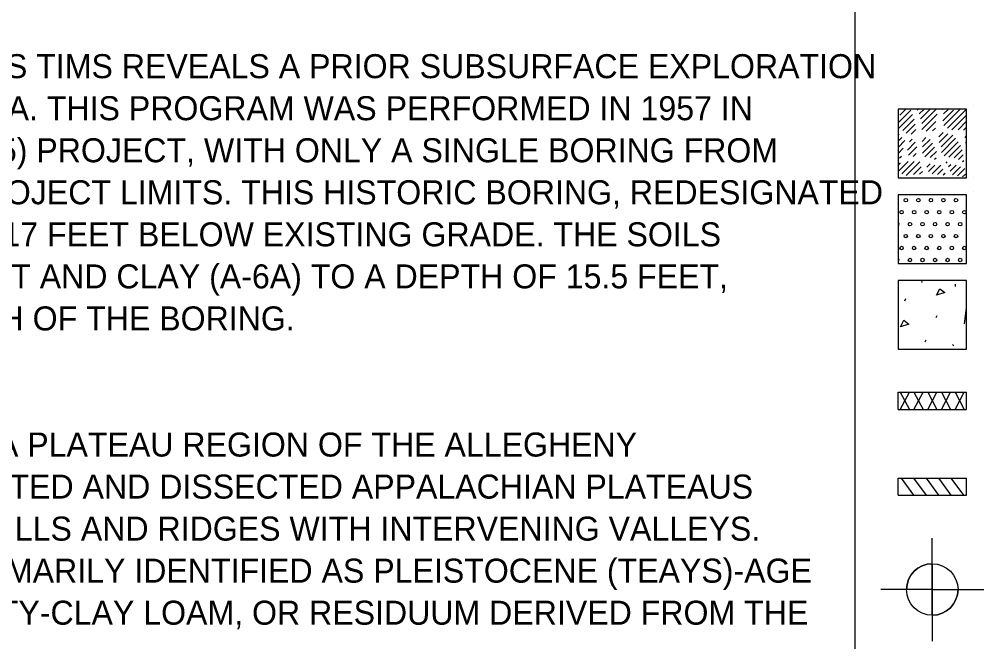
# Model space of a CAD drawing. Extents: x 0 to 34, y -8.9 to 22.
# Drawn here: x 6.83 to 12.45, y 14.31 to 17.94 of the extents above; entities that cross this region are included whole.
import ezdxf

# ---------------------------------------------------------------- set-up
doc = ezdxf.new("R2010")
doc.units = 0
for name, color, linetype in [('Default', 7, 'Continuous'), ('GT_Project_Soil_Boring', 7, 'Continuous'), ('GT_Project_Soil_Layers', 7, 'Continuous'), ('SH_Data', 7, 'Continuous'), ('SH_Text', 7, 'Continuous')]:
    doc.layers.add(name, color=color, linetype=linetype)

msp = doc.modelspace()

# ---------------------------------------------------------------- linework, layer by layer
at = {"layer": 'Default'}
for p, q in [((11.9545, 17.4334), (11.9545, 17.4334)), ((11.9597, 17.3384), (12.0303, 17.4089)), ((11.9652, 17.3792), (12.001, 17.415)), ((12.0664, 17.4097), (12.0717, 17.415)), ((12.0788, 17.3868), (12.107, 17.415)), ((12.0863, 17.3589), (12.1416, 17.4142)), ((12.0927, 17.33), (12.1767, 17.4139)), ((12.2121, 17.414), (12.2131, 17.415)), ((12.2158, 17.347), (12.2777, 17.4089)), ((12.2204, 17.3869), (12.2465, 17.413)), ((12.2228, 17.3187), (12.3178, 17.4136)), ((12.2437, 17.3041), (12.3493, 17.4098)), ((12.394, 17.4334), (12.394, 17.4334)), ((11.9602, 17.3035), (12.0398, 17.3832)), ((11.9827, 17.2907), (12.048, 17.356)), ((12.0939, 17.2958), (12.1827, 17.3846)), ((12.1187, 17.2853), (12.1752, 17.3418)), ((12.2694, 17.2945), (12.3545, 17.3797)), ((12.3048, 17.2945), (12.3545, 17.3443)), ((12.0029, 17.2755), (12.055, 17.3276)), ((12.0307, 17.2679), (12.058, 17.2953)), ((12.1563, 17.2875), (12.173, 17.3042)), ((12.1928, 17.2532), (12.2171, 17.2776)), ((12.3369, 17.2913), (12.3545, 17.3089)), ((11.9545, 17.2625), (11.9604, 17.2683)), ((11.9545, 17.2271), (11.9774, 17.25)), ((11.9545, 17.1918), (11.9944, 17.2316)), ((12.0099, 17.1764), (12.0548, 17.2214)), ((12.0219, 17.2237), (12.0372, 17.2391)), ((12.0953, 17.2265), (12.1175, 17.2486)), ((12.0971, 17.1575), (12.1561, 17.2166)), ((12.0983, 17.1941), (12.1418, 17.2376)), ((12.1945, 17.2196), (12.2454, 17.2705)), ((12.2055, 17.1953), (12.2739, 17.2637)), ((12.2074, 17.1618), (12.2906, 17.245)), ((12.2233, 17.1424), (12.3055, 17.2245)), ((12.3446, 17.2484), (12.3545, 17.2584)), ((12.3491, 17.2176), (12.3545, 17.223)), ((11.9545, 17.1564), (11.9846, 17.1865)), ((12.0162, 17.1473), (12.0639, 17.1951)), ((12.1119, 17.137), (12.1676, 17.1927)), ((12.142, 17.1318), (12.1783, 17.1681)), ((12.251, 17.1347), (12.3185, 17.2022)), ((12.2818, 17.1302), (12.3283, 17.1767)), ((11.9545, 17.0504), (12.013, 17.1088)), ((11.9637, 17.1302), (11.9747, 17.1412)), ((11.9771, 17.0376), (12.049, 17.1094)), ((12.0023, 17.0275), (12.0822, 17.1073)), ((12.0423, 17.1381), (12.061, 17.1569)), ((12.1682, 17.1226), (12.1763, 17.1307)), ((12.2346, 17.1001), (12.2415, 17.107)), ((12.3075, 17.1204), (12.3356, 17.1486)), ((12.3313, 17.1089), (12.3382, 17.1158)), ((11.9545, 17.0857), (11.9699, 17.1011)), ((12.0447, 17.0345), (12.0889, 17.0787)), ((12.0805, 17.0349), (12.0966, 17.0511)), ((12.123, 17.0774), (12.1421, 17.0965)), ((12.1331, 17.0521), (12.1691, 17.0882)), ((12.1536, 17.0373), (12.2038, 17.0875)), ((12.1845, 17.0329), (12.2156, 17.064)), ((12.2494, 17.0795), (12.2627, 17.0929)), ((12.2593, 17.054), (12.2936, 17.0884)), ((12.272, 17.0315), (12.3187, 17.0781)), ((12.3013, 17.0254), (12.3438, 17.0679)), ((11.9545, 17.015), (11.9545, 17.015)), ((12.2187, 17.0317), (12.2289, 17.0419)), ((12.3312, 17.0199), (12.3477, 17.0364)), ((12.394, 17.015), (12.394, 17.015)), ((11.9545, 16.9334), (11.9545, 16.9334)), ((12.394, 16.9334), (12.394, 16.9334)), ((11.9545, 16.7538), (11.9545, 16.7351)), ((11.9545, 16.5447), (11.9545, 16.526)), ((11.9545, 16.515), (11.9545, 16.515)), ((12.0918, 16.415), (12.0929, 16.4049)), ((12.2874, 16.3947), (12.2889, 16.3814)), ((11.9944, 16.2975), (12.0003, 16.3108)), ((12.1774, 16.1995), (12.1833, 16.2128)), ((12.3417, 16.1635), (12.3545, 16.256)), ((12.1125, 16.0578), (12.1185, 16.0711)), ((12.2733, 16.0439), (12.2793, 16.035)), ((11.9545, 16.015), (11.9545, 16.015))]:
    msp.add_line(p, q, dxfattribs=at)
for points in [[(12.1799, 16.3312), (12.1976, 16.3682), (12.2272, 16.346), (12.1799, 16.3312)], [(11.9698, 16.1469), (11.9876, 16.1839), (12.0172, 16.1617), (11.9698, 16.1469)]]:
    msp.add_lwpolyline(points, dxfattribs=at)
for centre in [(11.9999, 16.8839), (12.0731, 16.8839), (12.1463, 16.8839), (12.2196, 16.8839), (12.2928, 16.8839), (11.9754, 16.8142), (12.0486, 16.8142), (12.1219, 16.8142), (12.1951, 16.8142), (12.2684, 16.8142), (12.3415, 16.8142), (12.0242, 16.7445), (12.0974, 16.7445), (12.1707, 16.7445), (12.2439, 16.7445), (12.317, 16.7445), (11.9998, 16.6748), (12.073, 16.6748), (12.1462, 16.6748), (12.2195, 16.6748), (12.2926, 16.6748), (11.9753, 16.6051), (12.0485, 16.6051), (12.1218, 16.6051), (12.195, 16.6051), (12.2683, 16.6051), (12.3414, 16.6051), (12.0241, 16.5354), (12.0973, 16.5354), (12.1706, 16.5354), (12.2438, 16.5354), (12.3169, 16.5354)]:
    msp.add_circle(centre, 0.01, dxfattribs=at)
for centre, start, end in [((11.951, 16.7445), 290.8521, 69.1479), ((11.9509, 16.5354), 291.3407, 68.6593)]:
    msp.add_arc(centre, 0.01, start, end, dxfattribs=at)
at = {"layer": 'GT_Project_Soil_Boring'}
for p, q in [((12.1545, 14.615), (12.1545, 14.915)), ((12.1545, 14.765), (12.1545, 14.615)), ((12.1545, 14.615), (11.8545, 14.615)), ((12.1545, 14.615), (12.0045, 14.615)), ((12.1545, 14.615), (12.1545, 14.3149)), ((12.1545, 14.615), (12.4545, 14.615)), ((12.1545, 14.465), (12.1545, 14.615)), ((12.1545, 14.615), (12.3045, 14.615))]:
    msp.add_line(p, q, dxfattribs=at)
msp.add_circle((12.1545, 14.615), 0.15, dxfattribs=at)
for start, end in [(90, 180), (270, 360)]:
    msp.add_arc((12.1545, 14.615), 0.15, start, end, dxfattribs=at)
at = {"layer": 'GT_Project_Soil_Layers'}
for p, q in [((11.9678, 15.7649), (12.0212, 15.665)), ((11.9678, 15.665), (12.0212, 15.7649)), ((12.0478, 15.665), (12.1012, 15.7649)), ((12.0478, 15.7649), (12.1012, 15.665)), ((12.1278, 15.7649), (12.1812, 15.665)), ((12.1278, 15.665), (12.1812, 15.7649)), ((12.2078, 15.7649), (12.2612, 15.665)), ((12.2078, 15.665), (12.2612, 15.7649)), ((12.2878, 15.7649), (12.3412, 15.665)), ((12.2878, 15.665), (12.3412, 15.7649)), ((11.9727, 15.2649), (12.0454, 15.165)), ((12.0454, 15.2649), (12.1181, 15.165)), ((12.1181, 15.2649), (12.1909, 15.165)), ((12.1909, 15.2649), (12.2636, 15.165)), ((12.2636, 15.2649), (12.3363, 15.165))]:
    msp.add_line(p, q, dxfattribs=at)
at = {"layer": 'SH_Data'}
for p, q in [((11.7045, 1.1573), (11.7045, 21.5)), ((11.9545, 15.665), (11.9545, 15.7649)), ((11.9545, 15.7649), (12.3545, 15.7649)), ((12.3545, 15.665), (12.3545, 15.7649)), ((11.9545, 15.665), (12.3545, 15.665)), ((11.9545, 15.165), (11.9545, 15.2649)), ((11.9545, 15.2649), (12.3545, 15.2649)), ((12.3545, 15.165), (12.3545, 15.2649)), ((11.9545, 15.165), (12.3545, 15.165))]:
    msp.add_line(p, q, dxfattribs=at)
for points in [[(11.9545, 17.015), (12.3545, 17.015), (12.3545, 17.415), (11.9545, 17.415)], [(11.9545, 16.515), (12.3545, 16.515), (12.3545, 16.915), (11.9545, 16.915)], [(11.9545, 16.015), (12.3545, 16.015), (12.3545, 16.415), (11.9545, 16.415)]]:
    msp.add_lwpolyline(points, close=True, dxfattribs=at)

# ---------------------------------------------------------------- texts
at = {"layer": 'SH_Text'}
for s, p in [('A SEARCH OF THE AVAILABLE RECORDS ON ODOT’S TIMS REVEALS A PRIOR SUBSURFACE EXPLORATION ', (2.0379, 17.595)), ('PROGRAM PERFORMED WITHIN THE PROJECT AREA. THIS PROGRAM WAS PERFORMED IN 1957 IN ', (2.0379, 17.35)), ('SUPPORT OF THE NOB-147-18.28 (SUB-BATCH 14175) PROJECT, WITH ONLY A SINGLE BORING FROM ', (2.0379, 17.105)), ('THIS PROJECT LOCATED WITHIN THE CURRENT PROJECT LIMITS. THIS HISTORIC BORING, REDESIGNATED ', (2.0379, 16.86)), ('AS BORING B-001-1-57, EXTENDED TO A DEPTH OF 17 FEET BELOW EXISTING GRADE. THE SOILS ', (2.0379, 16.615)), ('ENCOUNTERED IN THIS BORING CONSISTED OF SILT AND CLAY (A-6A) TO A DEPTH OF 15.5 FEET, ', (2.0379, 16.37)), ('UNDERLAIN BY SHALE TO THE TERMINATION DEPTH OF THE BORING.', (2.0379, 16.125)), ('NOBLE COUNTY IS LOCATED WITHIN THE MARIETTA PLATEAU REGION OF THE ALLEGHENY ', (2.0379, 15.39)), ('(KANAWHA) PLATEAUS SECTION OF THE UNGLACIATED AND DISSECTED APPALACHIAN PLATEAUS ', (2.0379, 15.145)), ('PROVINCE, AND PRIMARILY CONSISTS OF STEEP HILLS AND RIDGES WITH INTERVENING VALLEYS. ', (2.0379, 14.9)), ('SOILS IN THE MARIETTA PLATEAU REGION ARE PRIMARILY IDENTIFIED AS PLEISTOCENE (TEAYS)-AGE ', (2.0379, 14.655)), ('MINFORD CLAYS, RED AND BROWN COLLUVIAL SILTY-CLAY LOAM, OR RESIDUUM DERIVED FROM THE ', (2.0379, 14.41))]:
    msp.add_text(s, height=0.14, dxfattribs=at).set_placement(p)

doc.saveas('drawing.dxf')
